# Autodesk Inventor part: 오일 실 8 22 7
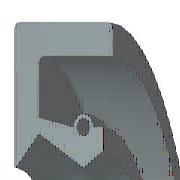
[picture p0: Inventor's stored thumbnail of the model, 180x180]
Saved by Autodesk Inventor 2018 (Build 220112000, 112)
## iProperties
IsCustomPart: 1
Created: 2012-02
Part Number: 오일 실 8 22 7
Material: 고무
Description: 오일-실
Document SubType Name: Modeling
Standard: KS B 2804
Designer: mduedu
Standards Organization: KS
Language: ko-KR
Size Designation: D - 8 22 7
Categories: <MemberInstance><Categories><Category DisplayName="샤프트 부품" InternalName="7f7aeb1f-a693-4053-b835-cee3144e0d98" Mnemonic="SHFT"><Category DisplayName="실링" Intern
Density: 0.93 g/cm^3
Appearance: 고무 - 검은색 - 버전 1.1
Author: mduedu
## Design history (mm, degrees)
revolve "본체" stored, may be unused: angle "d17" = 90 deg
revolve "스프링1" stored, may be unused: angle "d18" = 90 deg
body "Solid1"
sketch "스케치1"
  geometry: L1 (0, 11)-(7, 11); L2 (7, 9.25)-(1.75, 9.25); L3 (1.75, 5.75)-(4.9, 4); L4 (4.9, 4)-(0, 4); L5 (0, 0)-(9.586, 0) reference; L6 (4.9, 4)-(6.3, 4.875); L7 (0, 18)-(0, -3) reference; L8 (-1.941, 0)-(11.507, 0) reference; L9 (4.2, 6.1)-(1.75, 6.59); L10 (1.75, 6.59)-(1.75, 9.25); L11 (0, 11)-(0, 4.088); L12 (4.9, 4)-(0, 4); L13 (1.75, 5.75)-(0.152, 4.028); L14 (7, 11)-(7, 9.25); L15 (5.6, 6.1)-(6.3, 6.1); L16 (6.3, 6.1)-(6.3, 4.875); C1 r 0.455 at (4.9, 6.1); A1 r 0.7 centre (4.9, 6.1) between (5.6, 6.1) and (4.2, 6.1); A2 r 0.088 centre (0.088, 4.088) between (0, 4.088) and (0.152, 4.028); 1 further point
  constraints: 28 end point, 5 horizontal alignment, 5 point on line, 4 point on circle, 4 vertical alignment, 3 centre point, 3 tangent, 2 collinear, 2 horizontal, 2 perpendicular, 1 coincident, 1 parallel
  dimensions: "d0" = 22 diameter of L1 L5 (= SD2); "d1" = 1.75 distance of L1.end L2.start (= SD); "d2" = 0.91 diameter of C1 (= SPDI); "d3" = 1.4 diameter of A1 (= SPDA); "d4" = 8 diameter of L3.end L5 (= NND); "d5" = 11.5 diameter of L3.start L5 (= TKDM); "d7" = 13.18 diameter of L9.end L5 (= TKDM + 0.24 x SWDT); "d8" = 1.75 distance between parallel lines of L11 L10 (= SD); "d9" = 4.9 distance from line of L11 C1.centre (= SPDST); "d10" = 12.2 diameter of C1.centre L5 (= HLDM); "d11" = 0.0875 radius of A2 (= 0.25 x LAB); "d12" = 6.3 distance between parallel lines of L11 L16 (= SDI); "d13" = 9.75 diameter of L6.end L5 (= ABDM); "d14" = 7 distance from line of L11 L1.end (= SWDT)
fillet "모깎기1" dims "d6" = 0.3 (= RR)
other parameters: "SD2" = 22 [user parameter; used in 1 equation term], "SWDT" = 7 [user parameter; used in 2 equation terms], "RR" = 0.3 [user parameter; used in 1 equation term], "SD" = 1.75 [user parameter; used in 2 equation terms], "NND" = 8 [user parameter; used in 1 equation term], "SPDA" = 1.4 [user parameter; used in 1 equation term], "SPDI" = 0.91 [user parameter; used in 1 equation term], "TKDM" = 11.5 [user parameter; used in 2 equation terms], "HLDM" = 12.2 [user parameter; used in 1 equation term], "ABDM" = 9.75 [user parameter; used in 1 equation term], "SDI" = 6.3 [user parameter; used in 1 equation term], "SPDST" = 4.9 [user parameter; used in 1 equation term], "LAB" = 0.35 [user parameter; used in 1 equation term], "d15" = 0, "d16" = 0, "d19" = 0
